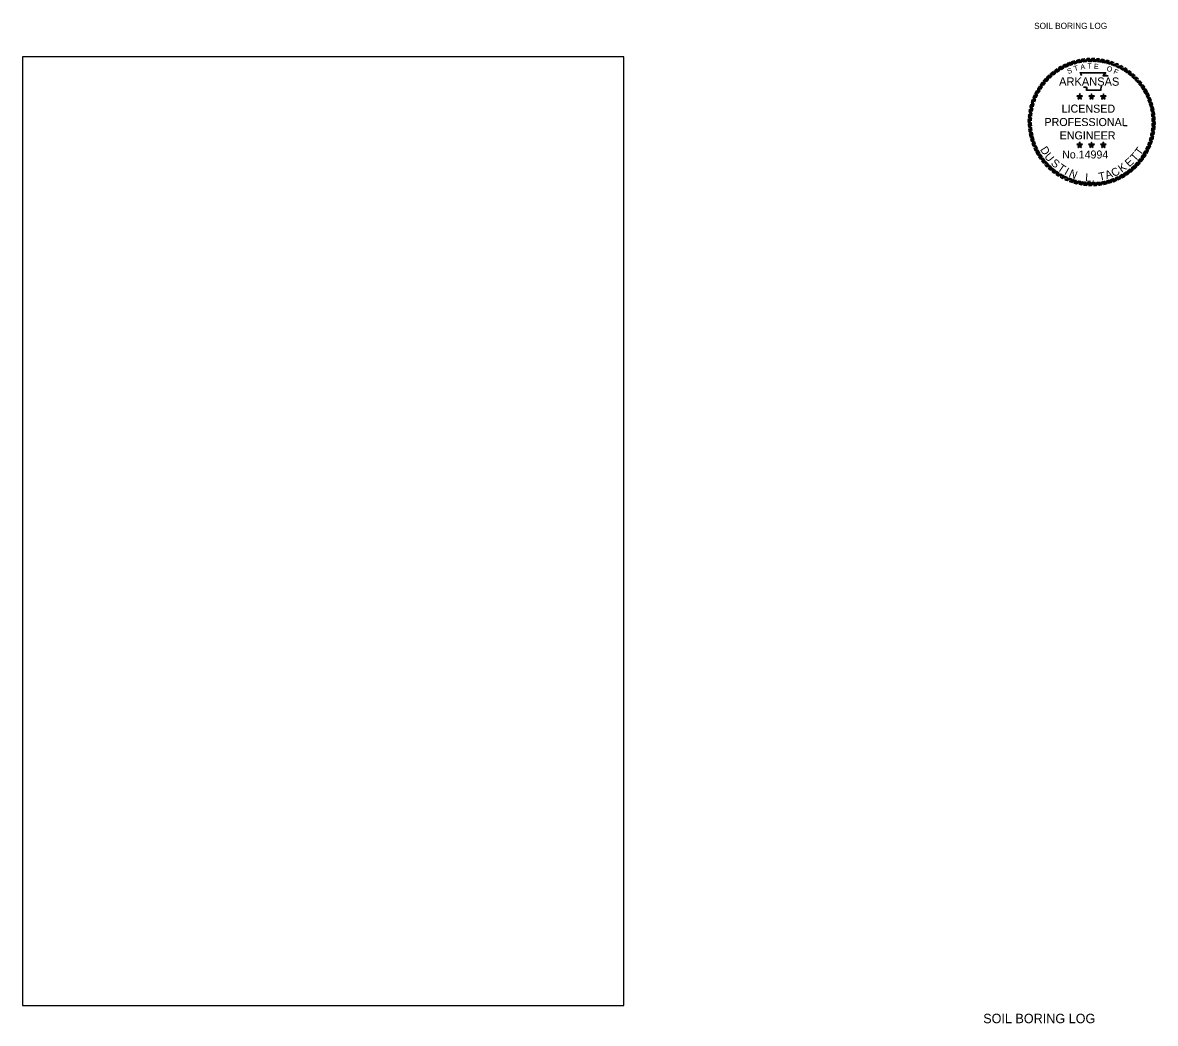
# Model space of a CAD drawing. Extents: x -36368.4 to -36346.8, y -1821462.3 to -1821443.2.
import ezdxf

# ---------------------------------------------------------------- set-up
doc = ezdxf.new("R2010")
doc.units = 0
for name, color, linetype in [('1', 7, 'Continuous'), ('29', 7, 'Continuous'), ('Default', 7, 'Continuous')]:
    doc.layers.add(name, color=color, linetype=linetype)

# ---------------------------------------------------------------- blocks, each defined once
blk = doc.blocks.new('STAR')
at = {"layer": 'Default'}
for p, q in [((0.059, 0.019), (-0.059, 0.019)), ((-0.059, 0.019), (0.036, -0.05)), ((0, 0.062), (-0.037, -0.05)), ((-0.036, -0.05), (0.059, 0.019)), ((-0.008, 0), (0.009, 0)), ((0.036, -0.05), (0, 0.062)), ((0, 0.006), (0, -0.008))]:
    blk.add_line(p, q, dxfattribs=at)
blk = doc.blocks.new('RP')
at = {"layer": 'Default'}
for p, q in [((-0.078, 1.266), (0.003, 1.33)), ((-0.058, 1.267), (0.022, 1.33)), ((-0.038, 1.267), (0.04, 1.329)), ((-0.018, 1.268), (0.059, 1.329))]:
    blk.add_line(p, q, dxfattribs=at)
for radius, start, end in [(1.268, 90.7933, 93.5307), (1.33, 87.4562, 89.8699)]:
    blk.add_arc((0, 0), radius, start, end, dxfattribs=at)

msp = doc.modelspace()

# ---------------------------------------------------------------- linework, layer by layer
at = {"layer": '1'}
msp.add_lwpolyline([(-36368.445, -1821462.003), (-36356.961, -1821462.003), (-36356.961, -1821443.896), (-36368.445, -1821443.896)], close=True, dxfattribs=at)
at = {"layer": 'Default'}
for points in [[(-36348.221, -1821444.259), (-36348.249, -1821444.197), (-36347.759, -1821444.197), (-36347.8, -1821444.248), (-36347.767, -1821444.248), (-36347.739, -1821444.248), (-36347.711, -1821444.251)], [(-36348.22, -1821444.258), (-36348.248, -1821444.197), (-36347.758, -1821444.198), (-36347.799, -1821444.25), (-36347.766, -1821444.249), (-36347.738, -1821444.249), (-36347.71, -1821444.252)], [(-36348.214, -1821444.255), (-36348.237, -1821444.205), (-36347.775, -1821444.205), (-36347.816, -1821444.256), (-36347.767, -1821444.256), (-36347.739, -1821444.255), (-36347.712, -1821444.258)], [(-36348.213, -1821444.255), (-36348.236, -1821444.205), (-36347.774, -1821444.206), (-36347.815, -1821444.257), (-36347.766, -1821444.257), (-36347.738, -1821444.257), (-36347.711, -1821444.26)], [(-36347.836, -1821444.464), (-36347.845, -1821444.471), (-36347.847, -1821444.481), (-36347.85, -1821444.507), (-36347.85, -1821444.54), (-36348.124, -1821444.54), (-36348.124, -1821444.495), (-36348.124, -1821444.485), (-36348.135, -1821444.481), (-36348.174, -1821444.481), (-36348.181, -1821444.471)], [(-36347.836, -1821444.465), (-36347.844, -1821444.472), (-36347.847, -1821444.482), (-36347.85, -1821444.507), (-36347.85, -1821444.541), (-36348.124, -1821444.54), (-36348.124, -1821444.495), (-36348.124, -1821444.485), (-36348.135, -1821444.481), (-36348.174, -1821444.481), (-36348.181, -1821444.47)], [(-36347.841, -1821444.458), (-36347.851, -1821444.467), (-36347.855, -1821444.48), (-36347.858, -1821444.506), (-36347.858, -1821444.533), (-36348.116, -1821444.533), (-36348.116, -1821444.495), (-36348.116, -1821444.479), (-36348.134, -1821444.473), (-36348.17, -1821444.473), (-36348.174, -1821444.466)], [(-36347.841, -1821444.459), (-36347.851, -1821444.467), (-36347.855, -1821444.481), (-36347.858, -1821444.507), (-36347.858, -1821444.534), (-36348.116, -1821444.533), (-36348.116, -1821444.495), (-36348.116, -1821444.479), (-36348.134, -1821444.473), (-36348.17, -1821444.473), (-36348.174, -1821444.466)]]:
    msp.add_lwpolyline(points, dxfattribs=at)

# ---------------------------------------------------------------- block references
for name, p, xscale, yscale, rotation in [('RP', (-36348.026, -1821445.141), 0.911765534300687, 0.9117655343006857, 13.500000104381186), ('RP', (-36348.028, -1821445.141), 0.9117655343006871, 0.9117655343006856, 13.30419999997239), ('RP', (-36348.026, -1821445.141), 0.9117655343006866, 0.911765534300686, 9.000000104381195), ('RP', (-36348.028, -1821445.141), 0.9117655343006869, 0.9117655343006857, 8.804199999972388), ('RP', (-36348.026, -1821445.141), 0.9117655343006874, 0.9117655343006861, 4.500000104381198), ('RP', (-36348.028, -1821445.141), 0.9117655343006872, 0.9117655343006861, 4.304199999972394), ('RP', (-36348.026, -1821445.141), 0.911765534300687, 0.9117655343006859, 1.0438120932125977e-07), ('RP', (-36348.028, -1821445.141), 0.911765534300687, 0.9117655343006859, -0.1958000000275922), ('RP', (-36348.026, -1821445.141), 0.9117655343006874, 0.9117655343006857, -4.499999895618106), ('RP', (-36348.028, -1821445.141), 0.9117655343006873, 0.9117655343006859, -4.695800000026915), ('RP', (-36348.026, -1821445.141), 0.9117655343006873, 0.911765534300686, -8.999999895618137), ('RP', (-36348.028, -1821445.141), 0.9117655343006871, 0.9117655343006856, -9.195800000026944), ('RP', (-36348.026, -1821445.141), 0.9117655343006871, 0.9117655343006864, -13.499999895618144), ('RP', (-36348.028, -1821445.141), 0.9117655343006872, 0.9117655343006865, -13.695800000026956), ('RP', (-36348.026, -1821445.141), 0.9117655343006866, 0.9117655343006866, 36.00000010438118), ('RP', (-36348.028, -1821445.141), 0.9117655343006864, 0.9117655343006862, 35.80419999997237), ('RP', (-36348.026, -1821445.141), 0.9117655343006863, 0.9117655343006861, 31.50000010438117), ('RP', (-36348.028, -1821445.141), 0.9117655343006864, 0.911765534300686, 31.304199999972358), ('RP', (-36348.026, -1821445.141), 0.9117655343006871, 0.9117655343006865, 27.000000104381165), ('RP', (-36348.028, -1821445.141), 0.9117655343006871, 0.9117655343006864, 26.80419999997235), ('RP', (-36348.026, -1821445.141), 0.9117655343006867, 0.9117655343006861, 22.500000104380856), ('RP', (-36348.028, -1821445.141), 0.911765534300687, 0.911765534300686, 22.304199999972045), ('RP', (-36348.026, -1821445.141), 0.9117655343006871, 0.9117655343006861, 18.000000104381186), ('RP', (-36348.028, -1821445.141), 0.9117655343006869, 0.9117655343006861, 17.80419999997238), ('RP', (-36348.026, -1821445.141), 0.9117655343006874, 0.9117655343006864, -17.999999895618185), ('RP', (-36348.028, -1821445.141), 0.9117655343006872, 0.9117655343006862, -18.19580000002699), ('RP', (-36348.026, -1821445.141), 0.9117655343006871, 0.9117655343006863, -22.4999998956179), ('RP', (-36348.028, -1821445.141), 0.9117655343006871, 0.9117655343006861, -22.695800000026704), ('RP', (-36348.026, -1821445.141), 0.9117655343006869, 0.9117655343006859, -26.999999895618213), ('RP', (-36348.028, -1821445.141), 0.9117655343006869, 0.911765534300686, -27.195800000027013), ('RP', (-36348.026, -1821445.141), 0.9117655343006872, 0.9117655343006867, -31.49999989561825), ('RP', (-36348.028, -1821445.141), 0.911765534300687, 0.9117655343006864, -31.69580000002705), ('RP', (-36348.026, -1821445.141), 0.9117655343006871, 0.9117655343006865, -35.99999989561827), ('RP', (-36348.028, -1821445.141), 0.9117655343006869, 0.9117655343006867, -36.19580000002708), ('RP', (-36348.026, -1821445.141), 0.9117655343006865, 0.9117655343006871, -40.49999989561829), ('RP', (-36348.028, -1821445.141), 0.9117655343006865, 0.9117655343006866, 53.804199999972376), ('RP', (-36348.026, -1821445.141), 0.9117655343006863, 0.9117655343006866, 54.00000010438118), ('RP', (-36348.026, -1821445.141), 0.9117655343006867, 0.9117655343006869, 49.50000010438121), ('RP', (-36348.028, -1821445.141), 0.9117655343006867, 0.9117655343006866, 49.3041999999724), ('RP', (-36348.026, -1821445.141), 0.9117655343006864, 0.9117655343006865, 45.00000010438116), ('RP', (-36348.028, -1821445.141), 0.9117655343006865, 0.9117655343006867, 44.80419999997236), ('RP', (-36348.026, -1821445.141), 0.9117655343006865, 0.9117655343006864, 40.50000010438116), ('RP', (-36348.028, -1821445.141), 0.9117655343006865, 0.9117655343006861, 40.30419999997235), ('RP', (-36348.028, -1821445.141), 0.9117655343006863, 0.9117655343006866, -40.69580000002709), ('RP', (-36348.026, -1821445.141), 0.9117655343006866, 0.9117655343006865, -44.999999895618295), ('RP', (-36348.028, -1821445.141), 0.9117655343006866, 0.9117655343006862, -45.19580000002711), ('RP', (-36348.026, -1821445.141), 0.9117655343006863, 0.9117655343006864, -49.499999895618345), ('RP', (-36348.028, -1821445.141), 0.9117655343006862, 0.9117655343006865, -49.695800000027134), ('RP', (-36348.026, -1821445.141), 0.9117655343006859, 0.9117655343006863, -53.99999989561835), ('RP', (-36348.028, -1821445.141), 0.9117655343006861, 0.9117655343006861, -54.195800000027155), ('RP', (-36348.028, -1821445.141), 0.9117655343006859, 0.9117655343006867, 62.80419999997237), ('RP', (-36348.026, -1821445.141), 0.9117655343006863, 0.9117655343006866, 63.000000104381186), ('RP', (-36348.028, -1821445.141), 0.9117655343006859, 0.9117655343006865, 58.30419999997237), ('RP', (-36348.026, -1821445.141), 0.911765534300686, 0.9117655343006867, 58.50000010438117), ('STAR', (-36348.256, -1821444.656), 0.911765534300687, 0.9117655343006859, -0.1958000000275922), ('STAR', (-36348.255, -1821444.657), 0.911765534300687, 0.9117655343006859, 1.0438120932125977e-07), ('STAR', (-36348.03, -1821444.657), 0.911765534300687, 0.9117655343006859, -0.1958000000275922), ('STAR', (-36348.03, -1821444.657), 0.911765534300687, 0.9117655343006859, 1.0438120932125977e-07), ('STAR', (-36347.804, -1821444.657), 0.911765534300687, 0.9117655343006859, 1.0438120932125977e-07), ('STAR', (-36347.804, -1821444.658), 0.911765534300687, 0.9117655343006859, -0.1958000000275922), ('RP', (-36348.026, -1821445.141), 0.9117655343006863, 0.9117655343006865, -58.499999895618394), ('RP', (-36348.028, -1821445.141), 0.9117655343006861, 0.9117655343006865, -58.6958000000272), ('RP', (-36348.026, -1821445.141), 0.9117655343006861, 0.9117655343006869, -62.999999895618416), ('RP', (-36348.028, -1821445.141), 0.911765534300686, 0.9117655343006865, -63.19580000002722), ('RP', (-36348.028, -1821445.141), 0.911765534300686, 0.9117655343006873, 76.3041999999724), ('RP', (-36348.026, -1821445.141), 0.9117655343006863, 0.9117655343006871, 76.5000001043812), ('RP', (-36348.028, -1821445.141), 0.9117655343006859, 0.9117655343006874, 71.80419999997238), ('RP', (-36348.026, -1821445.141), 0.9117655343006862, 0.9117655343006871, 72.00000010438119), ('RP', (-36348.028, -1821445.141), 0.9117655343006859, 0.9117655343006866, 67.30419999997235), ('RP', (-36348.026, -1821445.141), 0.9117655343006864, 0.9117655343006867, 67.50000010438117), ('RP', (-36348.028, -1821445.141), 0.9117655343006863, 0.911765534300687, -67.69580000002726), ('RP', (-36348.026, -1821445.141), 0.9117655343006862, 0.9117655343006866, -67.49999989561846), ('RP', (-36348.026, -1821445.141), 0.9117655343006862, 0.911765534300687, -71.99999989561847), ('RP', (-36348.028, -1821445.141), 0.9117655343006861, 0.9117655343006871, -72.19580000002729), ('RP', (-36348.028, -1821445.141), 0.9117655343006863, 0.9117655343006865, -76.6958000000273), ('RP', (-36348.026, -1821445.141), 0.9117655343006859, 0.9117655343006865, -76.4999998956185), ('RP', (-36348.028, -1821445.141), 0.9117655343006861, 0.9117655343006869, 85.3041999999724), ('RP', (-36348.026, -1821445.141), 0.911765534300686, 0.9117655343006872, 85.5000001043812), ('RP', (-36348.028, -1821445.141), 0.9117655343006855, 0.9117655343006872, 80.8041999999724), ('RP', (-36348.026, -1821445.141), 0.9117655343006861, 0.9117655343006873, 81.00000010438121), ('RP', (-36348.028, -1821445.141), 0.9117655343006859, 0.911765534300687, -81.19580000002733), ('RP', (-36348.026, -1821445.141), 0.9117655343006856, 0.9117655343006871, -80.99999989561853), ('RP', (-36348.028, -1821445.141), 0.9117655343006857, 0.911765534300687, -85.69580000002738), ('RP', (-36348.026, -1821445.141), 0.9117655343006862, 0.9117655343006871, -85.49999989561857), ('RP', (-36348.028, -1821445.141), 0.9117655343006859, 0.9117655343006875, 94.30419999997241), ('RP', (-36348.028, -1821445.141), 0.9117655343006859, 0.9117655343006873, 89.80419999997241), ('RP', (-36348.026, -1821445.141), 0.9117655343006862, 0.9117655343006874, 90.00000010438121), ('RP', (-36348.026, -1821445.141), 0.9117655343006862, 0.9117655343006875, 94.50000010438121), ('RP', (-36348.028, -1821445.141), 0.9117655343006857, 0.9117655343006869, -99.19580000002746), ('RP', (-36348.026, -1821445.141), 0.9117655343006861, 0.9117655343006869, -98.99999989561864), ('RP', (-36348.028, -1821445.141), 0.911765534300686, 0.911765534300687, -94.69580000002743), ('RP', (-36348.026, -1821445.141), 0.9117655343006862, 0.9117655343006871, -94.49999989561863), ('RP', (-36348.028, -1821445.141), 0.9117655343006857, 0.9117655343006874, -90.19580000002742), ('RP', (-36348.026, -1821445.141), 0.9117655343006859, 0.9117655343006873, -89.99999989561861), ('RP', (-36348.028, -1821445.141), 0.9117655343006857, 0.9117655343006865, 98.80419999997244), ('RP', (-36348.026, -1821445.141), 0.9117655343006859, 0.9117655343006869, 99.00000010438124), ('RP', (-36348.028, -1821445.141), 0.911765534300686, 0.911765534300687, 103.3041999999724), ('RP', (-36348.026, -1821445.141), 0.911765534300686, 0.9117655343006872, 103.50000010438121), ('RP', (-36348.028, -1821445.141), 0.911765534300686, 0.9117655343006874, 107.80419999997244), ('RP', (-36348.026, -1821445.141), 0.9117655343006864, 0.9117655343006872, 108.00000010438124), ('RP', (-36348.028, -1821445.141), 0.9117655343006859, 0.9117655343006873, -108.19580000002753), ('RP', (-36348.026, -1821445.141), 0.9117655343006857, 0.9117655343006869, -107.99999989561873), ('RP', (-36348.028, -1821445.141), 0.911765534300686, 0.911765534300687, -103.6958000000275), ('RP', (-36348.026, -1821445.141), 0.9117655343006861, 0.9117655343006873, -103.4999998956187), ('RP', (-36348.028, -1821445.141), 0.9117655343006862, 0.911765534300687, 112.30419999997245), ('RP', (-36348.026, -1821445.141), 0.9117655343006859, 0.9117655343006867, 112.50000010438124), ('RP', (-36348.028, -1821445.141), 0.9117655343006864, 0.9117655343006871, 116.80419999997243), ('RP', (-36348.026, -1821445.141), 0.9117655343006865, 0.9117655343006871, 117.0000001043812), ('STAR', (-36348.259, -1821445.581), 0.911765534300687, 0.9117655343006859, -0.1958000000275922), ('STAR', (-36348.255, -1821445.582), 0.911765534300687, 0.9117655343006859, 1.0438120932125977e-07), ('STAR', (-36348.033, -1821445.582), 0.911765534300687, 0.9117655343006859, -0.1958000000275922), ('STAR', (-36348.03, -1821445.582), 0.911765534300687, 0.9117655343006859, 1.0438120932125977e-07), ('STAR', (-36347.808, -1821445.583), 0.911765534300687, 0.9117655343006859, -0.1958000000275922), ('STAR', (-36347.804, -1821445.582), 0.911765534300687, 0.9117655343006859, 1.0438120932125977e-07), ('RP', (-36348.028, -1821445.141), 0.9117655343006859, 0.911765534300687, -121.6958000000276), ('RP', (-36348.026, -1821445.141), 0.9117655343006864, 0.9117655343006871, -121.4999998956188), ('RP', (-36348.028, -1821445.141), 0.9117655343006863, 0.9117655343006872, -117.1958000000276), ('RP', (-36348.026, -1821445.141), 0.9117655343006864, 0.9117655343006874, -116.9999998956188), ('RP', (-36348.028, -1821445.141), 0.9117655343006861, 0.9117655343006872, -112.69580000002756), ('RP', (-36348.026, -1821445.141), 0.9117655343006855, 0.9117655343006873, -112.49999989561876), ('RP', (-36348.028, -1821445.141), 0.9117655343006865, 0.9117655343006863, 121.30419999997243), ('RP', (-36348.026, -1821445.141), 0.9117655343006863, 0.911765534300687, 121.50000010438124), ('RP', (-36348.028, -1821445.141), 0.911765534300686, 0.9117655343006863, 125.80419999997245), ('RP', (-36348.026, -1821445.141), 0.9117655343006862, 0.9117655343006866, 126.00000010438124), ('RP', (-36348.028, -1821445.141), 0.9117655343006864, 0.9117655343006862, 130.30419999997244), ('RP', (-36348.026, -1821445.141), 0.9117655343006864, 0.9117655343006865, 130.50000010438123), ('RP', (-36348.028, -1821445.141), 0.9117655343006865, 0.9117655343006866, -130.69580000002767), ('RP', (-36348.026, -1821445.141), 0.9117655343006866, 0.911765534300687, -130.49999989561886), ('RP', (-36348.028, -1821445.141), 0.9117655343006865, 0.9117655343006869, -126.19580000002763), ('RP', (-36348.026, -1821445.141), 0.9117655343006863, 0.911765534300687, -125.99999989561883), ('RP', (-36348.028, -1821445.141), 0.9117655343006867, 0.9117655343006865, 134.80419999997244), ('RP', (-36348.026, -1821445.141), 0.9117655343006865, 0.9117655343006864, 135.00000010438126), ('RP', (-36348.028, -1821445.141), 0.9117655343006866, 0.9117655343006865, 139.3041999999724), ('RP', (-36348.026, -1821445.141), 0.9117655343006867, 0.9117655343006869, 139.5000001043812), ('RP', (-36348.028, -1821445.141), 0.9117655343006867, 0.9117655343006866, 143.80419999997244), ('RP', (-36348.026, -1821445.141), 0.9117655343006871, 0.9117655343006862, 144.00000010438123), ('RP', (-36348.028, -1821445.141), 0.9117655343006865, 0.9117655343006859, 148.3041999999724), ('RP', (-36348.026, -1821445.141), 0.9117655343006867, 0.911765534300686, 148.50000010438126), ('RP', (-36348.028, -1821445.141), 0.9117655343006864, 0.9117655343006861, -148.69580000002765), ('RP', (-36348.026, -1821445.141), 0.9117655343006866, 0.911765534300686, -148.49999989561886), ('RP', (-36348.028, -1821445.141), 0.9117655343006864, 0.9117655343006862, -144.19580000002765), ('RP', (-36348.026, -1821445.141), 0.9117655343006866, 0.9117655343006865, -143.99999989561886), ('RP', (-36348.028, -1821445.141), 0.9117655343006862, 0.9117655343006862, -139.69580000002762), ('RP', (-36348.026, -1821445.141), 0.9117655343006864, 0.911765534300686, -139.49999989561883), ('RP', (-36348.028, -1821445.141), 0.9117655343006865, 0.9117655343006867, -135.19580000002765), ('RP', (-36348.026, -1821445.141), 0.9117655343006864, 0.9117655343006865, -134.99999989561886), ('RP', (-36348.028, -1821445.141), 0.911765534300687, 0.9117655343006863, 152.8041999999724), ('RP', (-36348.026, -1821445.141), 0.9117655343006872, 0.9117655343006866, 153.00000010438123), ('RP', (-36348.028, -1821445.141), 0.911765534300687, 0.9117655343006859, 157.30419999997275), ('RP', (-36348.026, -1821445.141), 0.911765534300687, 0.9117655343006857, 157.50000010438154), ('RP', (-36348.028, -1821445.141), 0.9117655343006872, 0.9117655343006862, 161.8041999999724), ('RP', (-36348.026, -1821445.141), 0.9117655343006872, 0.9117655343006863, 162.00000010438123), ('RP', (-36348.028, -1821445.141), 0.9117655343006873, 0.911765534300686, 166.3041999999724), ('RP', (-36348.026, -1821445.141), 0.9117655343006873, 0.911765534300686, 166.50000010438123), ('RP', (-36348.028, -1821445.141), 0.9117655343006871, 0.9117655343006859, 170.8041999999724), ('RP', (-36348.026, -1821445.141), 0.9117655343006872, 0.911765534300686, 171.00000010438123), ('RP', (-36348.028, -1821445.141), 0.911765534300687, 0.911765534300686, 175.3041999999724), ('RP', (-36348.026, -1821445.141), 0.9117655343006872, 0.911765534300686, 175.50000010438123), ('RP', (-36348.028, -1821445.141), 0.9117655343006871, 0.9117655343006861, 179.80419999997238), ('RP', (-36348.026, -1821445.141), 0.9117655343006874, 0.9117655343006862, -179.9999998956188), ('RP', (-36348.028, -1821445.141), 0.9117655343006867, 0.911765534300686, -175.69580000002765), ('RP', (-36348.026, -1821445.141), 0.9117655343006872, 0.911765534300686, -175.49999989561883), ('RP', (-36348.028, -1821445.141), 0.9117655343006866, 0.911765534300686, -171.19580000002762), ('RP', (-36348.026, -1821445.141), 0.9117655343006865, 0.9117655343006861, -170.99999989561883), ('RP', (-36348.028, -1821445.141), 0.9117655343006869, 0.9117655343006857, -166.69580000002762), ('RP', (-36348.026, -1821445.141), 0.9117655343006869, 0.9117655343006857, -166.49999989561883), ('RP', (-36348.028, -1821445.141), 0.911765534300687, 0.9117655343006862, -162.1958000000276), ('RP', (-36348.026, -1821445.141), 0.9117655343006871, 0.9117655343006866, -161.9999998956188), ('RP', (-36348.028, -1821445.141), 0.9117655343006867, 0.9117655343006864, -157.695800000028), ('RP', (-36348.026, -1821445.141), 0.9117655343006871, 0.9117655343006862, -157.49999989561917), ('RP', (-36348.028, -1821445.141), 0.9117655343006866, 0.9117655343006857, -153.19580000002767), ('RP', (-36348.026, -1821445.141), 0.9117655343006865, 0.9117655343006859, -152.99999989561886)]:
    msp.add_blockref(name, p, dxfattribs=dict(at, xscale=xscale, yscale=yscale, rotation=rotation))

# ---------------------------------------------------------------- texts
at = {"layer": '1'}
msp.add_text('SOIL BORING LOG', height=0.11724, dxfattribs=at).set_placement((-36349.126, -1821443.364))
at = {"layer": '29'}
msp.add_text('SOIL BORING LOG', height=0.18, dxfattribs=at).set_placement((-36350.099, -1821462.343))
at = {"layer": 'Default'}
for s, height, rotation, p in [('S', 0.0967, 19.7726, (-36348.476, -1821444.226)), ('S', 0.0967, 19.5768, (-36348.475, -1821444.225)), ('T', 0.0967, 16.9015, (-36348.353, -1821444.171)), ('T', 0.0967, 16.7057, (-36348.352, -1821444.17)), ('A', 0.0967, 8.6788, (-36348.236, -1821444.141)), ('A', 0.0967, 8.483, (-36348.235, -1821444.14)), ('T', 0.0967, 1.4789, (-36348.111, -1821444.121)), ('T', 0.0967, 1.2831, (-36348.11, -1821444.121)), ('E', 0.0967, 356.672, (-36347.987, -1821444.124)), ('E', 0.0967, 356.4762, (-36347.986, -1821444.125)), ('O', 0.0967, 341.2218, (-36347.752, -1821444.157)), ('O', 0.0967, 341.026, (-36347.751, -1821444.159)), ('F', 0.0967, 335.3628, (-36347.622, -1821444.208)), ('F', 0.0967, 335.167, (-36347.621, -1821444.21)), ('ARKANSAS', 0.1579, 0, (-36348.65, -1821444.447)), ('ARKANSAS', 0.1579, 359.8042, (-36348.65, -1821444.445)), ('LICENSED', 0.1528, 359.8042, (-36348.603, -1821444.96)), ('LICENSED', 0.1528, 0, (-36348.601, -1821444.962)), ('PROFESSIONAL', 0.15285, 359.8042, (-36348.931, -1821445.215)), ('PROFESSIONAL', 0.15285, 0, (-36348.929, -1821445.218)), ('ENGINEER', 0.1528, 359.8042, (-36348.641, -1821445.471)), ('ENGINEER', 0.1528, 0, (-36348.638, -1821445.473)), ('D', 0.153, 302.9045, (-36349.02, -1821445.667)), ('No.14994', 0.1522, 0, (-36348.593, -1821445.837)), ('T', 0.153, 54.3036, (-36347.096, -1821445.793)), ('U', 0.153, 309.8131, (-36348.942, -1821445.803)), ('S', 0.153, 320.368, (-36348.819, -1821445.946)), ('E', 0.153, 42.4392, (-36347.31, -1821446.009)), ('T', 0.153, 48.0746, (-36347.195, -1821445.906)), ('T', 0.153, 325.101, (-36348.696, -1821446.05)), ('I', 0.153, 330.8687, (-36348.564, -1821446.135)), ('N', 0.153, 337.2539, (-36348.476, -1821446.177)), ('T', 0.153, 11.7303, (-36347.879, -1821446.263)), ('A', 0.153, 19.3817, (-36347.742, -1821446.234)), ('C', 0.153, 33.6577, (-36347.595, -1821446.199)), ('K', 0.153, 35.1218, (-36347.455, -1821446.112)), ('L', 0.153, 358.474, (-36348.152, -1821446.275)), ('.', 0.153, 4.1489, (-36348.028, -1821446.283))]:
    msp.add_text(s, height=height, rotation=rotation, dxfattribs=at).set_placement(p)

doc.saveas('drawing.dxf')
